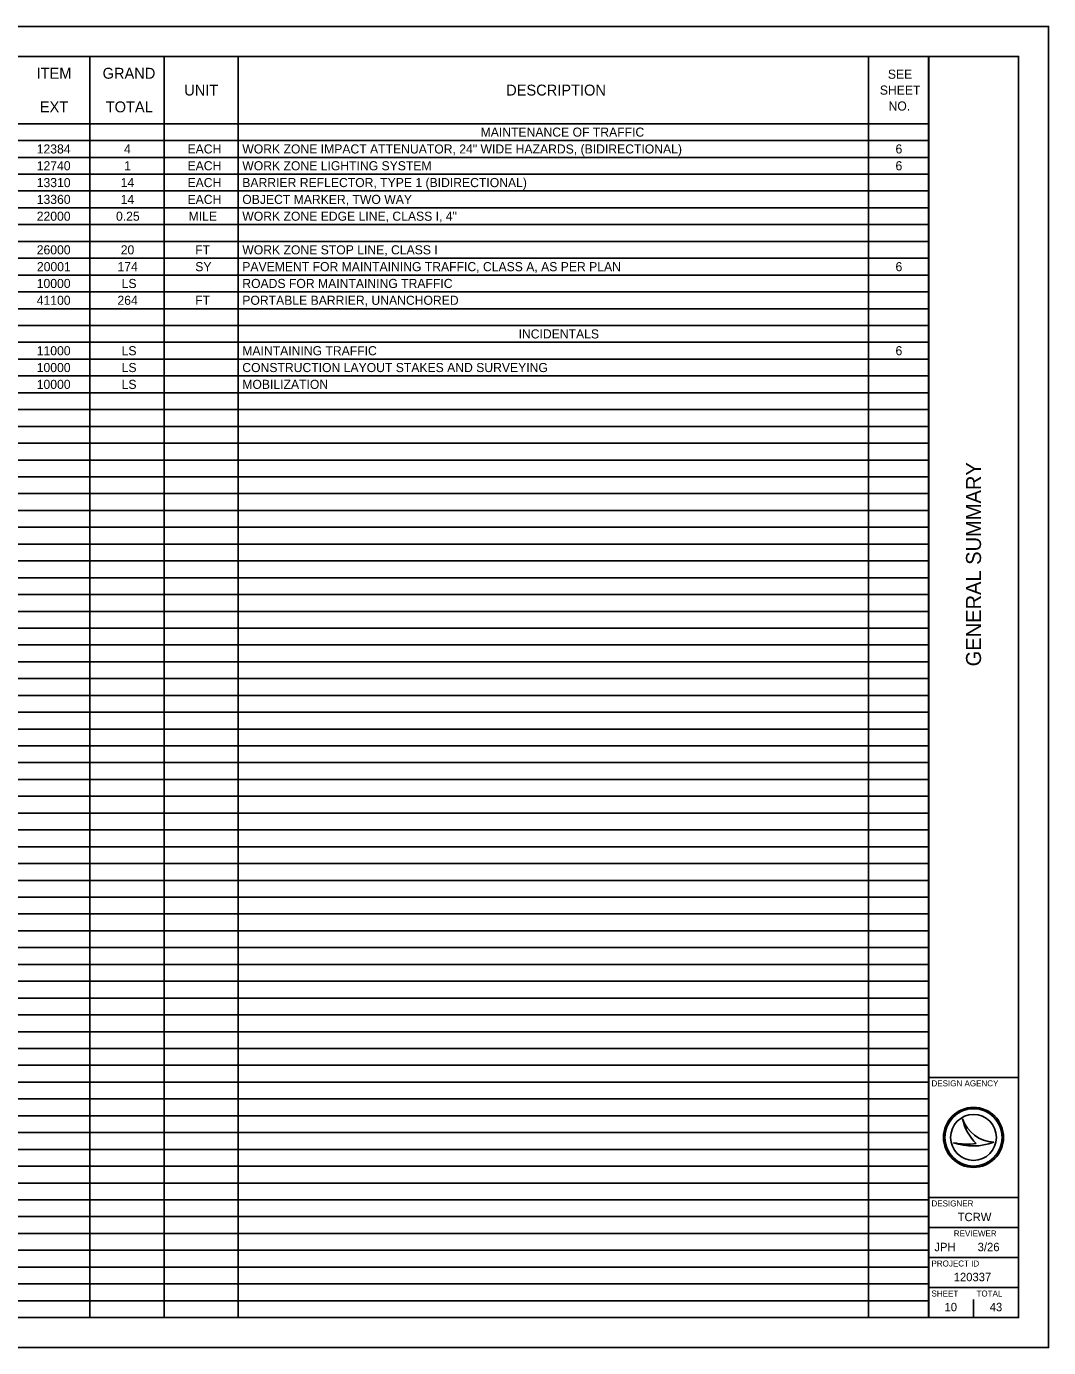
# Model space of a CAD drawing. Extents: x 0 to 34, y 0 to 22.
# Drawn here: x 16.98 to 34, y 0 to 22 of the extents above; entities that cross this region are included whole.
import ezdxf

# ---------------------------------------------------------------- set-up
doc = ezdxf.new("R2010")
doc.units = 0
for name, color, linetype in [('Default', 7, 'Continuous'), ('SH_Border', 7, 'Continuous'), ('SH_Cut_Line', 7, 'Continuous'), ('SH_Data', 7, 'Continuous')]:
    doc.layers.add(name, color=color, linetype=linetype)

msp = doc.modelspace()

# ---------------------------------------------------------------- linework, layer by layer
at = {"layer": 'Default'}
for p, q in [((1.5, 21.5), (32.004, 21.5)), ((18.036, 21.5), (18.036, 0.5)), ((19.272, 21.5), (19.272, 0.5)), ((20.507, 21.5), (20.507, 0.5)), ((30.999, 21.5), (30.999, 0.5)), ((32.004, 21.5), (32.004, 0.5)), ((1.5, 20.38), (32.004, 20.38)), ((1.5, 20.1), (32.004, 20.1)), ((1.5, 19.82), (32.004, 19.82)), ((1.5, 19.54), (32.004, 19.54)), ((1.5, 19.26), (32.004, 19.26)), ((1.5, 18.98), (32.004, 18.98)), ((1.5, 18.7), (32.004, 18.7)), ((1.5, 18.42), (32.004, 18.42)), ((1.5, 18.14), (32.004, 18.14)), ((1.5, 17.86), (32.004, 17.86)), ((1.5, 17.58), (32.004, 17.58)), ((1.5, 17.3), (32.004, 17.3)), ((1.5, 17.02), (32.004, 17.02)), ((1.5, 16.74), (32.004, 16.74)), ((1.5, 16.46), (32.004, 16.46)), ((1.5, 16.18), (32.004, 16.18)), ((1.5, 15.9), (32.004, 15.9)), ((1.5, 15.62), (32.004, 15.62)), ((1.5, 15.34), (32.004, 15.34)), ((1.5, 15.06), (32.004, 15.06)), ((1.5, 14.78), (32.004, 14.78)), ((1.5, 14.5), (32.004, 14.5)), ((1.5, 14.22), (32.004, 14.22)), ((1.5, 13.94), (32.004, 13.94)), ((1.5, 13.66), (32.004, 13.66)), ((1.5, 13.38), (32.004, 13.38)), ((1.5, 13.1), (32.004, 13.1)), ((1.5, 12.82), (32.004, 12.82)), ((1.5, 12.54), (32.004, 12.54)), ((1.5, 12.26), (32.004, 12.26)), ((1.5, 11.98), (32.004, 11.98)), ((1.5, 11.7), (32.004, 11.7)), ((1.5, 11.42), (32.004, 11.42)), ((1.5, 11.14), (32.004, 11.14)), ((1.5, 10.86), (32.004, 10.86)), ((1.5, 10.58), (32.004, 10.58)), ((1.5, 10.3), (32.004, 10.3)), ((1.5, 10.02), (32.004, 10.02)), ((1.5, 9.74), (32.004, 9.74)), ((1.5, 9.46), (32.004, 9.46)), ((1.5, 9.18), (32.004, 9.18)), ((1.5, 8.9), (32.004, 8.9)), ((1.5, 8.62), (32.004, 8.62)), ((1.5, 8.34), (32.004, 8.34)), ((1.5, 8.06), (32.004, 8.06)), ((1.5, 7.78), (32.004, 7.78)), ((1.5, 7.5), (32.004, 7.5)), ((1.5, 7.22), (32.004, 7.22)), ((1.5, 6.94), (32.004, 6.94)), ((1.5, 6.66), (32.004, 6.66)), ((1.5, 6.38), (32.004, 6.38)), ((1.5, 6.1), (32.004, 6.1)), ((1.5, 5.82), (32.004, 5.82)), ((1.5, 5.54), (32.004, 5.54)), ((1.5, 5.26), (32.004, 5.26)), ((1.5, 4.98), (32.004, 4.98)), ((1.5, 4.7), (32.004, 4.7)), ((1.5, 4.42), (32.004, 4.42)), ((1.5, 4.14), (32.004, 4.14)), ((1.5, 3.86), (32.004, 3.86)), ((1.5, 3.58), (32.004, 3.58)), ((1.5, 3.3), (32.004, 3.3)), ((1.5, 3.02), (32.004, 3.02)), ((1.5, 2.74), (32.004, 2.74)), ((1.5, 2.46), (32.004, 2.46)), ((1.5, 2.18), (32.004, 2.18)), ((1.5, 1.9), (32.004, 1.9)), ((1.5, 1.62), (32.004, 1.62)), ((1.5, 1.34), (32.004, 1.34)), ((1.5, 1.06), (32.004, 1.06)), ((1.5, 0.78), (32.004, 0.78)), ((1.5, 0.5), (32.004, 0.5))]:
    msp.add_line(p, q, dxfattribs=at)
at = {"layer": 'SH_Border'}
for p, q in [((32, 0.5), (32, 21.5)), ((32, 4.5), (33.5, 4.5)), ((32, 2.5), (33.5, 2.5)), ((32, 2), (33.5, 2)), ((32, 1.5), (33.5, 1.5)), ((32, 1), (33.5, 1))]:
    msp.add_line(p, q, dxfattribs=at)
msp.add_lwpolyline([(1.5, 21.5), (33.5, 21.5), (33.5, 0.5), (1.5, 0.5)], close=True, dxfattribs=at)
at = {"layer": 'SH_Cut_Line'}
msp.add_lwpolyline([(0, 0), (34, 0), (34, 22), (0, 22)], close=True, dxfattribs=at)
at = {"layer": 'SH_Data'}
for p, q in [((32.567, 3.81), (32.567, 3.81)), ((32.417, 3.41), (32.417, 3.41)), ((32.75, 3.5), (32.75, 3.5)), ((33.087, 3.419), (33.087, 3.419)), ((32.375, 0.675), (32.375, 0.675)), ((32.75, 0.5), (32.75, 0.8))]:
    msp.add_line(p, q, dxfattribs=at)
for radius in [0.5, 0.477, 0.477, 0.382]:
    msp.add_circle((32.75, 3.5), radius, dxfattribs=at)
for centre, radius, start, end in [((33.116, 3.998), 0.58, 198.9257, 198.9319), ((33.347, 3.97), 0.796, 191.6379, 191.6421), ((33.116, 3.998), 0.58, 198.9319, 267.1657), ((33.347, 3.97), 0.796, 191.6421, 226.0947), ((32.739, 4.37), 1.013, 251.4576, 290.0832), ((32.648, 4.654), 1.266, 259.4964, 259.4995), ((32.739, 4.37), 1.013, 251.4527, 251.4576), ((32.648, 4.654), 1.266, 259.4995, 276.6672)]:
    msp.add_arc(centre, radius, start, end, dxfattribs=at)

# ---------------------------------------------------------------- texts
at = {"layer": 'Default'}
for s, height, p in [('ITEM', 0.1818, (17.147, 21.129)), ('GRAND', 0.1818, (18.247, 21.129)), ('SEE ', 0.1515, (31.324, 21.129)), ('UNIT', 0.1818, (19.606, 20.849)), ('DESCRIPTION', 0.18184, (24.967, 20.849)), ('SHEET ', 0.1515, (31.19, 20.864)), ('EXT', 0.1818, (17.201, 20.569)), ('TOTAL', 0.1818, (18.299, 20.569)), ('NO.', 0.1515, (31.335, 20.599)), ('MAINTENANCE OF TRAFFIC', 0.15153, (24.542, 20.164)), ('12384', 0.1515, (17.15, 19.884)), ('4', 0.152, (18.603, 19.884)), ('EACH', 0.1515, (19.661, 19.884)), ('WORK ZONE IMPACT ATTENUATOR, 24" WIDE HAZARDS, (BIDIRECTIONAL)', 0.15153, (20.573, 19.884)), ('6', 0.152, (31.451, 19.884)), ('12740', 0.1515, (17.15, 19.604)), ('1', 0.152, (18.606, 19.604)), ('EACH', 0.1515, (19.661, 19.604)), ('WORK ZONE LIGHTING SYSTEM', 0.15153, (20.573, 19.604)), ('6', 0.152, (31.451, 19.604)), ('13310', 0.1515, (17.15, 19.324)), ('14', 0.1515, (18.548, 19.324)), ('EACH', 0.1515, (19.661, 19.324)), ('BARRIER REFLECTOR, TYPE 1 (BIDIRECTIONAL)', 0.15153, (20.573, 19.324)), ('13360', 0.1515, (17.15, 19.044)), ('14', 0.1515, (18.548, 19.044)), ('EACH', 0.1515, (19.661, 19.044)), ('OBJECT MARKER, TWO WAY', 0.15153, (20.573, 19.044)), ('22000', 0.1515, (17.15, 18.764)), ('0.25', 0.1515, (18.47, 18.764)), ('MILE', 0.1515, (19.679, 18.764)), ('WORK ZONE EDGE LINE, CLASS I, 4"', 0.15153, (20.573, 18.764)), ('26000', 0.1515, (17.15, 18.204)), ('20', 0.1515, (18.549, 18.204)), ('FT', 0.1515, (19.789, 18.204)), ('WORK ZONE STOP LINE, CLASS I', 0.15153, (20.573, 18.204)), ('20001', 0.1515, (17.153, 17.924)), ('174', 0.1515, (18.494, 17.924)), ('SY', 0.1515, (19.79, 17.924)), ('PAVEMENT FOR MAINTAINING TRAFFIC, CLASS A, AS PER PLAN', 0.15153, (20.573, 17.924)), ('6', 0.152, (31.451, 17.924)), ('10000', 0.1515, (17.15, 17.644)), ('LS', 0.1515, (18.564, 17.644)), ('ROADS FOR MAINTAINING TRAFFIC', 0.15153, (20.573, 17.644)), ('41100', 0.1515, (17.15, 17.364)), ('264', 0.1515, (18.494, 17.364)), ('FT', 0.1515, (19.789, 17.364)), ('PORTABLE BARRIER, UNANCHORED', 0.15153, (20.573, 17.364)), ('INCIDENTALS', 0.15153, (25.174, 16.804)), ('11000', 0.1515, (17.15, 16.524)), ('LS', 0.1515, (18.564, 16.524)), ('MAINTAINING TRAFFIC', 0.15153, (20.573, 16.524)), ('6', 0.152, (31.451, 16.524)), ('10000', 0.1515, (17.15, 16.244)), ('LS', 0.1515, (18.564, 16.244)), ('CONSTRUCTION LAYOUT STAKES AND SURVEYING', 0.15153, (20.573, 16.244)), ('10000', 0.1515, (17.15, 15.964)), ('LS', 0.1515, (18.564, 15.964)), ('MOBILIZATION', 0.15153, (20.573, 15.964))]:
    msp.add_text(s, height=height, dxfattribs=at).set_placement(p)
at = {"layer": 'SH_Data'}
msp.add_text('GENERAL SUMMARY', height=0.25, rotation=90, dxfattribs=at).set_placement((32.875, 11.344))
for s, height, p in [('DESIGN AGENCY', 0.1, (32.05, 4.35)), ('DESIGNER', 0.1, (32.05, 2.35)), ('TCRW', 0.14, (32.486, 2.105)), ('REVIEWER', 0.1, (32.422, 1.85)), ('JPH', 0.14, (32.098, 1.605)), ('3/26', 0.14, (32.819, 1.605)), ('PROJECT ID', 0.1, (32.05, 1.35)), ('120337', 0.14, (32.42, 1.105)), ('SHEET', 0.1, (32.05, 0.85)), ('TOTAL', 0.1, (32.8, 0.85)), ('10', 0.14, (32.267, 0.605)), ('43', 0.14, (33.02, 0.605))]:
    msp.add_text(s, height=height, dxfattribs=at).set_placement(p)

doc.saveas('drawing.dxf')
